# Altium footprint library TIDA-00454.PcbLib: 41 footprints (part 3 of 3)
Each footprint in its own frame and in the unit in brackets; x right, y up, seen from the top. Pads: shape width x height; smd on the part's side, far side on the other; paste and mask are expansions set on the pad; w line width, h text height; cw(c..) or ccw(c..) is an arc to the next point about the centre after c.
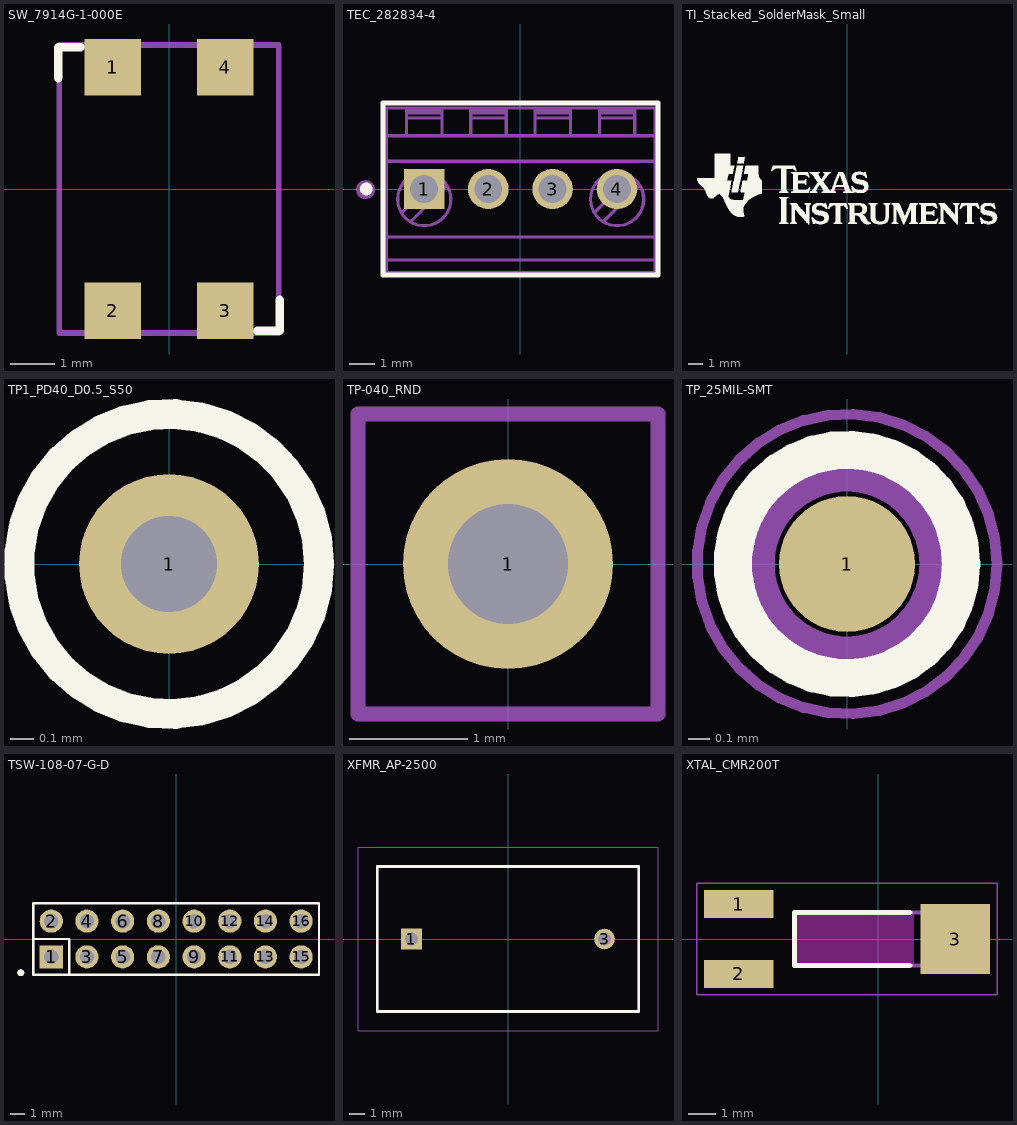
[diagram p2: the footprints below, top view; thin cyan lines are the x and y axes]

## SW_7914G-1-000E [mm] "BOURNS"
height 4.49
pads (4):
  rect 1.27x1.27 smd mask+0.064: 1(-1.27,2.75) 2(-1.27,-2.75) 3(1.27,-2.75) 4(1.27,2.75)
Top Overlay:
  lines w0.2: -2.5,2.5 -2.5,3.2 -2,3.2 ; 2,-3.2 2.5,-3.2 2.5,-2.5
Mechanical 5:
  lines w0.127: -2.48,-3.25 -2.48,3.25 2.48,3.25 2.48,-3.25 -2.48,-3.25
  text ".Designator" at -0.762,0.762 h0.76
3D body: height 2.54, standoff 0, extent -2.249,-2.499 2.249,2.499
3D body: height 4.49, standoff 2, extent -1.21,-1.21 1.21,1.21

## TEC_282834-4 [mm] "TEC"
height 10.3
pads (4):
  rect 1.6x1.6 hole 1.1 mask+0.064: 1(-3.81,0)
  round 1.6 hole 1.1 mask+0.064: 2(-1.27,0) 3(1.27,0) 4(3.81,0)
Top Overlay:
  circle w0.3: c-6.096,0 r0.1
  lines w0.2: -5.435,-3.4 -5.435,3.4 5.435,3.4 5.435,-3.4 -5.435,-3.4
Mechanical 5:
  circle w0.152: c-6.121,-0.025 r0.297
  circle w0.3: c-6.096,0 r0.1
  lines w0.127: -4.698,-0.944 -3.256,0.498 ; -4.5,2.8 -3.1,2.8 ; -4.5,3 -3.1,3 ; -4.5,3.1 -3.1,3.1 ; -4.344,-1.298 -2.902,0.144 ; -1.96,2.8 -0.56,2.8 ; -1.96,3 -0.56,3 ; -1.96,3.1 -0.56,3.1 ; 0.58,2.8 1.98,2.8 ; 0.58,3 1.98,3 ; 0.58,3.1 1.98,3.1 ; 2.922,-0.944 4.364,0.498 ; 3.12,2.8 4.52,2.8 ; 3.12,3 4.52,3 ; 3.12,3.1 4.52,3.1 ; 3.276,-1.298 4.718,0.144 ; -5.3,-2.8 5.32,-2.8 ; -5.3,-2.8 -5.3,-3.3 5.32,-3.3 5.32,-2.8 ; -5.3,-2.8 -5.3,-1.9 ; -5.3,-1.9 -5.3,1.1 ; -5.3,-1.9 5.32,-1.9 ; -5.3,1.1 -5.3,2.1 ; -5.3,1.1 5.32,1.1 ; -5.3,2.1 -5.3,2.9 -5.3,3.2 -4.5,3.2 ; -5.3,2.1 -4.5,2.1 ; -4.5,2.1 -4.5,2.9 -4.5,3.2 ; -4.5,2.1 -3.1,2.1 ; -4.5,3.2 -3.1,3.2 ; -3.1,2.1 -1.96,2.1 ; -3.1,2.1 -3.1,2.9 -3.1,3.2 ; -3.1,3.2 -1.96,3.2 ; -1.96,2.1 -0.56,2.1 ; -1.96,2.1 -1.96,2.9 -1.96,3.2 ; -1.96,3.2 -0.56,3.2 ; -0.56,2.1 -0.56,2.9 -0.56,3.2 ; -0.56,2.1 0.58,2.1 ; -0.56,3.2 0.58,3.2 ; 0.58,2.1 0.58,2.9 0.58,3.2 ; 0.58,2.1 1.98,2.1 ; 0.58,3.2 1.98,3.2 ; 1.98,2.1 1.98,2.9 1.98,3.2 ; 1.98,2.1 3.12,2.1 ; 1.98,3.2 3.12,3.2 ; 3.12,2.1 4.52,2.1 ; 3.12,2.1 3.12,2.9 3.12,3.2 ; 3.12,3.2 4.52,3.2 ; 4.52,2.1 5.32,2.1 ; 4.52,2.1 4.52,2.9 4.52,3.2 ; 4.52,3.2 5.32,3.2 5.32,2.9 5.32,2.1 ; 5.32,-2.8 5.32,-1.9 ; 5.32,-1.9 5.32,1.1 ; 5.32,1.1 5.32,2.1 ; -4.85,-0.4 cw(c-3.8,-0.4) -2.75,-0.4 cw(c-3.8,-0.4) -4.85,-0.4 ; 2.77,-0.4 cw(c3.82,-0.4) 4.87,-0.4 cw(c3.82,-0.4) 2.77,-0.4
  text ".Designator" at 0.457,-5.029 h0.76
3D body: height 10.02, standoff -3.38, extent -5.31,-3.25 5.31,3.25

## TI_Stacked_SolderMask_Small [mm]
Top Overlay:
  drawing of 18 lines, arcs and shapes, not listed

## TP1_PD40_D0.5_S50 [mil]
height 1.4
pads (1):
  round 30 hole 16 mask+2.5: 1(0,0)
Top Overlay:
  circle w5: c0,0 r25

## TP-040_RND [mil]
height 444.88
pads (1):
  round 70 / inner round 62 / far side round 62 hole 40 mask+2.5: 1(0,0)
Mechanical 5:
  lines w5: -50,-50 50,-50 50,50 -50,50 -50,-50
  text ".Designator" at -15,145 h30

## TP_25MIL-SMT [mm] "SMT, TESTPOINT"
height 11.3
pads (1):
  round 0.635 smd mask+0.064: 1(0,0)
Top Overlay:
  circle w0.178: c0,0 r0.533
Mechanical 5:
  circle w0.127: c0,0 r0.402
  text ".Designator" at 0.381,-3.556 h0.76
Mechanical 15:
  circle w0.05: c0,0 r0.7
3D body: height 0.05, standoff 0, extent -0.399,-0.401 0.402,0.401

## TSW-108-07-G-D [mm] "Samtec 100mil, 2x8, 230 mil above insulator"
height 8.382
pads (16):
  rect 1.65x1.65 hole 1.016 mask+0.064: 1(-8.89,-1.27)
  round 1.65 hole 1.016 mask+0.064: 2(-8.89,1.27) 3(-6.35,-1.27) 4(-6.35,1.27) 5(-3.81,-1.27) 6(-3.81,1.27) 7(-1.27,-1.27) 8(-1.27,1.27) 9(1.27,-1.27) 10(1.27,1.27) 11(3.81,-1.27) 12(3.81,1.27) 13(6.35,-1.27) 14(6.35,1.27) 15(8.89,-1.27) 16(8.89,1.27)
Top Overlay:
  circle w0.25: c-11.06,-2.4 r0.125
  lines w0.178: -10.16,0 -7.62,0 -7.62,-2.54 ; -10.16,-2.54 -10.16,2.54 10.16,2.54 10.16,-2.54 -10.16,-2.54
Mechanical 5:
  rectangle: -9.398,-1.778 -8.382,-0.762
  lines w0.127: -10.16,-2.54 10.16,-2.54 10.16,2.54 -10.16,2.54 -10.16,-2.54
  text ".Designator" at -1.549,0.508 h0.76
3D body: height 8.38, standoff -2.54, extent -10.16,-2.54 10.16,2.54

## XFMR_AP-2500 [mm] "TRANSFORMER, TH"
height 20.4
pads (2):
  rect 1.354x1.354 / inner round 1.354 / far side rect 1.354x1.354 hole 0.854 mask+0.064: 1(-6.35,0)
  round 1.354 hole 0.854 mask+0.064: 3(6.35,0)
Top Overlay:
  lines w0.178: -8.6,-4.765 -8.6,4.765 8.6,4.765 8.6,-4.765 -8.6,-4.765
Bottom Overlay:
  lines w0.178: -8.6,-3.846 -8.6,-3 ; -8.6,-1.846 -8.6,-1 ; -8.6,0.154 -8.6,1 ; -8.6,2.154 -8.6,3 ; -8.6,3.937 -8.6,4.783 ; -7.001,-4.765 -6.107,-4.765 ; -7.001,4.765 -6.051,4.765 ; -5.001,-4.765 -4.107,-4.765 ; -5.001,4.765 -4.051,4.765 ; -3.001,-4.765 -2.107,-4.765 ; -3.001,4.765 -2.051,4.765 ; -1.001,-4.765 -0.107,-4.765 ; -1.001,4.765 -0.051,4.765 ; 0.999,-4.765 1.893,-4.765 ; 0.999,4.765 1.949,4.765 ; 2.999,-4.765 3.893,-4.765 ; 2.999,4.765 3.949,4.765 ; 4.999,-4.765 5.893,-4.765 ; 4.999,4.765 5.949,4.765 ; 6.999,-4.765 7.893,-4.765 ; 6.999,4.765 7.949,4.765 ; 8.6,-3.955 8.6,-3 ; 8.6,-1.955 8.6,-1 ; 8.6,0.045 8.6,1 ; 8.6,2.045 8.6,3 ; 8.6,3.714 8.6,4.668
Mechanical 5:
  lines w0.127: -8.6,-4.765 -8.6,4.765 8.6,4.765 8.6,-4.765 -8.6,-4.765
  text ".Designator" at 0.583,0.381 h0.76
Mechanical 15:
  lines w0.05: -9.87,-6.035 -9.87,6.035 9.87,6.035 9.87,-6.035 -9.87,-6.035
Mechanical 17:
  text "LEAD LENGTH:4.00 MM" at -12.7,9.144 h1.52
3D body: height 20.4, standoff 0, extent -8.6,-4.765 8.6,4.765

## XTAL_CMR200T [mm] "XTAL, SMD, 3-PIN"
height 2
pads (3):
  rect 2.5x1 smd mask+0.064: 1(-5,1.25) 2(-5,-1.25)
  rect 2.5x2.5 smd mask+0.064: 3(2.75,0)
Top Layer keep-out:
  rectangle: -3.048,-0.946 1.272,0.954
Top Overlay:
  lines w0.178: 1.125,-0.95 -3,-0.95 -3,0.95 1.125,0.95
  text ".Designator" at -0.254,-2.667 h1.02
Mechanical 5:
  lines w0.127: -3,-0.95 3,-0.95 3,0.95 -3,0.95 -3,-0.95
  text ".Designator" at -0.635,-0.381 h0.76
Mechanical 15:
  lines w0.05: -6.5,-2 4.25,-2 4.25,2 -6.5,2 -6.5,-2
3D body: height 2, standoff 0, extent -3,-0.95 3,0.95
